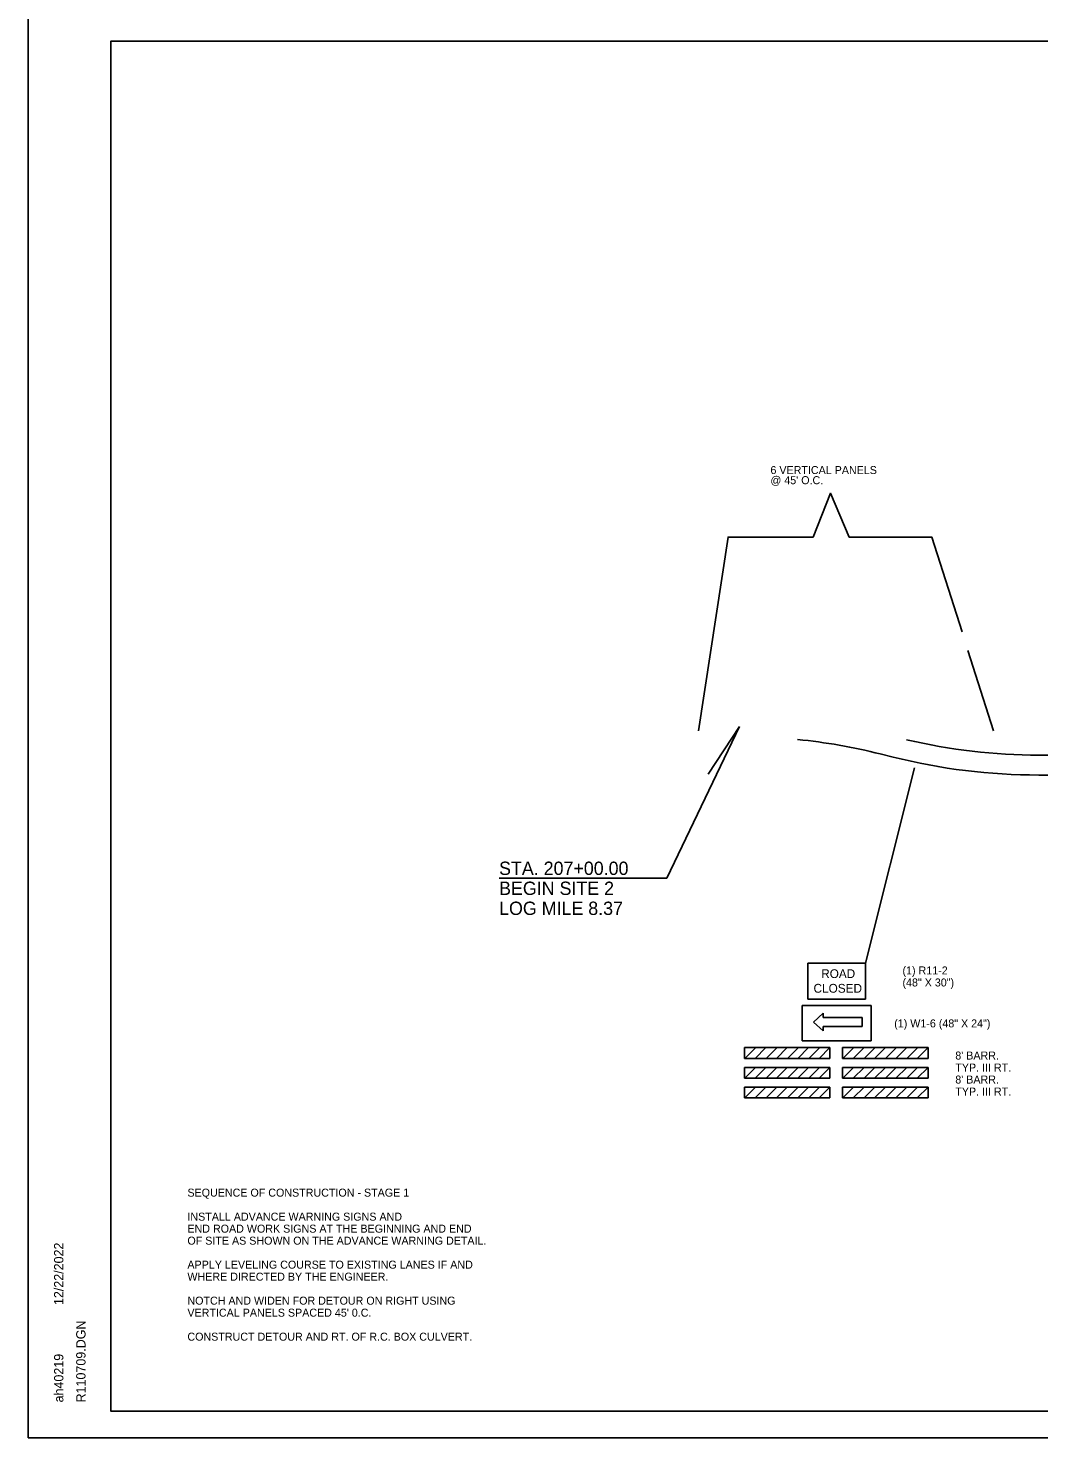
# Model space of a CAD drawing. Extents: x 2829243 to 2838161, y 467639 to 474695.
# Drawn here: x 2829486 to 2830244, y 470445 to 471502 of the extents above; entities that cross this region are included whole.
import ezdxf

# ---------------------------------------------------------------- set-up
doc = ezdxf.new("R2010")
doc.units = 0
for name, color, linetype in [('R_Border', 7, 'Continuous'), ('R_Border Notes', 7, 'Continuous'), ('R_Dimension', 7, 'Continuous'), ('R_MOT', 7, 'Continuous'), ('R_No Plot', 7, 'Continuous')]:
    doc.layers.add(name, color=color, linetype=linetype)

msp = doc.modelspace()

# ---------------------------------------------------------------- linework, layer by layer
at = {"layer": 'R_Border'}
for p, q in [((2829548.2, 471492.3), (2831129.1, 471492.3)), ((2829548.2, 470465), (2829548.2, 471492.3)), ((2829548.2, 470465), (2829548.2, 470465)), ((2831129.1, 470465), (2829548.2, 470465))]:
    msp.add_line(p, q, dxfattribs=at)
at = {"layer": 'R_Dimension'}
for p, q in [((2829965.2, 470864.6), (2830019.6, 470978.4)), ((2829996, 470942.8), (2830019.6, 470978.4)), ((2829965.2, 470864.6), (2829839.3, 470864.6))]:
    msp.add_line(p, q, dxfattribs=at)
at = {"layer": 'R_MOT'}
for p, q in [((2830070.7, 470773.9), (2830070.7, 470801)), ((2830070.7, 470801), (2830114.1, 470801)), ((2830114.1, 470773.9), (2830114.1, 470801)), ((2830070.7, 470773.9), (2830114.1, 470773.9)), ((2830075, 470756.8), (2830082.2, 470763.4)), ((2830082.2, 470750.3), (2830075, 470756.8)), ((2830082.2, 470760.1), (2830082.2, 470763.4)), ((2830111.6, 470760.1), (2830082.2, 470760.1)), ((2830111.6, 470753.5), (2830111.6, 470760.1)), ((2830111.6, 470753.5), (2830082.2, 470753.5)), ((2830082.2, 470753.5), (2830082.2, 470750.3)), ((2830023.4, 470737.7), (2830087.4, 470737.7)), ((2830023.4, 470729.6), (2830023.4, 470737.7)), ((2830087.4, 470729.6), (2830087.4, 470737.7)), ((2830096.9, 470737.7), (2830161, 470737.7)), ((2830096.9, 470729.6), (2830096.9, 470737.7)), ((2830161, 470729.6), (2830161, 470737.7)), ((2830023.4, 470729.6), (2830087.4, 470729.6)), ((2830087.4, 470729.6), (2830087.4, 470729.7)), ((2830096.9, 470729.6), (2830161, 470729.6)), ((2830160.9, 470729.6), (2830161, 470729.7)), ((2830023.4, 470722.8), (2830087.4, 470722.8)), ((2830023.4, 470714.7), (2830023.4, 470722.8)), ((2830023.4, 470714.7), (2830087.4, 470714.7)), ((2830087.4, 470714.7), (2830087.4, 470722.8)), ((2830087.4, 470714.7), (2830087.4, 470722.8)), ((2830096.9, 470722.8), (2830161, 470722.8)), ((2830096.9, 470714.7), (2830096.9, 470722.8)), ((2830096.9, 470714.7), (2830161, 470714.7)), ((2830161, 470714.7), (2830161, 470722.8)), ((2830161, 470714.7), (2830161, 470722.8)), ((2830023.4, 470707.9), (2830087.4, 470707.9)), ((2830023.4, 470699.9), (2830023.4, 470707.9)), ((2830087.4, 470699.9), (2830087.4, 470707.9)), ((2830096.9, 470707.9), (2830161, 470707.9)), ((2830096.9, 470699.9), (2830096.9, 470707.9)), ((2830161, 470699.9), (2830161, 470707.9)), ((2830023.4, 470699.9), (2830087.4, 470699.9)), ((2830096.9, 470699.9), (2830161, 470699.9))]:
    msp.add_line(p, q, dxfattribs=at)
for points in [[(2830186.5, 471049.3), (2830163.8, 471120.4), (2830101.8, 471120.4), (2830087.8, 471153.3), (2830074.8, 471120.4), (2830011, 471120.4), (2829988.9, 470975.2)], [(2830210.1, 470975.2), (2830190.9, 471035.4)], [(2830114.1, 470801), (2830150.9, 470947.4)]]:
    msp.add_lwpolyline(points, dxfattribs=at)
for points in [[(2830066.6, 470742.8), (2830118.2, 470742.8), (2830118.2, 470769.1), (2830066.6, 470769.1)], [(2830039.4, 470737.7), (2830031.6, 470737.6), (2830023.6, 470729.6), (2830031.4, 470729.6)], [(2830055.4, 470737.7), (2830047.6, 470737.6), (2830039.6, 470729.6), (2830047.4, 470729.6)], [(2830071.4, 470737.7), (2830063.6, 470737.6), (2830055.6, 470729.6), (2830063.4, 470729.6)], [(2830087.4, 470737.7), (2830079.6, 470737.6), (2830071.6, 470729.6), (2830079.4, 470729.6)], [(2830113, 470737.7), (2830105.1, 470737.6), (2830097.1, 470729.6), (2830104.9, 470729.6)], [(2830129, 470737.7), (2830121.1, 470737.6), (2830113.1, 470729.6), (2830120.9, 470729.6)], [(2830145, 470737.7), (2830137.1, 470737.6), (2830129.1, 470729.6), (2830136.9, 470729.6)], [(2830161, 470737.7), (2830153.1, 470737.6), (2830145.1, 470729.6), (2830152.9, 470729.6)], [(2830039.4, 470722.8), (2830031.6, 470722.7), (2830023.6, 470714.7), (2830031.4, 470714.7)], [(2830055.4, 470722.8), (2830047.6, 470722.7), (2830039.6, 470714.7), (2830047.4, 470714.7)], [(2830071.4, 470722.8), (2830063.6, 470722.7), (2830055.6, 470714.7), (2830063.4, 470714.7)], [(2830087.4, 470722.8), (2830079.6, 470722.7), (2830071.6, 470714.7), (2830079.4, 470714.7)], [(2830113, 470722.8), (2830105.1, 470722.7), (2830097.1, 470714.7), (2830104.9, 470714.7)], [(2830129, 470722.8), (2830121.1, 470722.7), (2830113.1, 470714.7), (2830120.9, 470714.7)], [(2830145, 470722.8), (2830137.1, 470722.7), (2830129.1, 470714.7), (2830136.9, 470714.7)], [(2830161, 470722.8), (2830153.1, 470722.7), (2830145.1, 470714.7), (2830152.9, 470714.7)], [(2830039.4, 470707.9), (2830031.6, 470707.9), (2830023.6, 470699.9), (2830031.4, 470699.9)], [(2830055.4, 470707.9), (2830047.6, 470707.9), (2830039.6, 470699.9), (2830047.4, 470699.9)], [(2830071.4, 470707.9), (2830063.6, 470707.9), (2830055.6, 470699.9), (2830063.4, 470699.9)], [(2830087.4, 470707.9), (2830079.6, 470707.9), (2830071.6, 470699.9), (2830079.4, 470699.9)], [(2830113, 470707.9), (2830105.1, 470707.9), (2830097.1, 470699.9), (2830104.9, 470699.9)], [(2830129, 470707.9), (2830121.1, 470707.9), (2830113.1, 470699.9), (2830120.9, 470699.9)], [(2830145, 470707.9), (2830137.1, 470707.9), (2830129.1, 470699.9), (2830136.9, 470699.9)], [(2830161, 470707.9), (2830153.1, 470707.9), (2830145.1, 470699.9), (2830152.9, 470699.9)]]:
    msp.add_lwpolyline(points, close=True, dxfattribs=at)
at = {"layer": 'R_No Plot'}
for p, q in [((2830125.1, 470957.9), (2830134.8, 470955.4)), ((2830244, 470956.9), (2830365.9, 470956.9)), ((2830244, 470941.9), (2830365.9, 470941.9)), ((2829486.2, 470445.1), (2831152.9, 470445.1))]:
    msp.add_line(p, q, dxfattribs=at)
for points in [[(2829486.2, 471511.8), (2831152.9, 471511.8), (2831152.9, 470445.1), (2829486.2, 470445.1)], [(2830717.8, 471492.3), (2830815.9, 471492.3), (2830815.9, 471442.9), (2830896.5, 471442.9), (2831012.5, 471442.9), (2831012.5, 471321.2), (2831129.1, 471321.2), (2831129.1, 470465), (2829548.2, 470465), (2829548.2, 471492.3)]]:
    msp.add_lwpolyline(points, close=True, dxfattribs=at)
for centre, radius, start, end in [((2830019.6, 470537.7), 433.2, 75.8983, 84.2308), ((2830244, 471390.2), 433.2, 256.7695, 270), ((2830244, 471390.2), 448.2, 255.8983, 270)]:
    msp.add_arc(centre, radius, start, end, dxfattribs=at)

# ---------------------------------------------------------------- texts
at = {"layer": 'R_Border'}
for s, p in [('12/22/2022', (2829512.6, 470544.6)), ('R110709.DGN', (2829529.2, 470471.6)), ('ah40219', (2829512.6, 470471.6))]:
    msp.add_text(s, height=7, rotation=90, dxfattribs=at).set_placement(p)
at = {"layer": 'R_Border Notes'}
for s, p in [('SEQUENCE OF CONSTRUCTION - STAGE 1', (2829605.6, 470625.9)), ('INSTALL ADVANCE WARNING SIGNS AND ', (2829605.6, 470607.9)), ('END ROAD WORK SIGNS AT THE BEGINNING AND END', (2829605.6, 470598.9)), ('OF SITE AS SHOWN ON THE ADVANCE WARNING DETAIL.', (2829605.6, 470589.9)), ('APPLY LEVELING COURSE TO EXISTING LANES IF AND', (2829605.6, 470571.9)), ('WHERE DIRECTED BY THE ENGINEER.', (2829605.6, 470562.9)), ('NOTCH AND WIDEN FOR DETOUR ON RIGHT USING', (2829605.6, 470544.9)), ("VERTICAL PANELS SPACED 45' 0.C.", (2829605.6, 470535.9)), ('CONSTRUCT DETOUR AND RT. OF R.C. BOX CULVERT.', (2829605.6, 470517.9))]:
    msp.add_text(s, height=6, dxfattribs=at).set_placement(p)
at = {"layer": 'R_Dimension'}
for s, p in [('STA. 207+00.00', (2829839.3, 470867.1)), ('BEGIN SITE 2', (2829839.3, 470852.1)), ('LOG MILE 8.37', (2829839.3, 470837.1))]:
    msp.add_text(s, height=10, rotation=0.0006, dxfattribs=at).set_placement(p)
at = {"layer": 'R_MOT'}
for s, p in [('6 VERTICAL PANELS', (2830042.8, 471167.7)), ("@ 45' O.C.", (2830042.8, 471160.1))]:
    msp.add_text(s, height=6, rotation=0.0055, dxfattribs=at).set_placement(p)
for s, height, p in [('(1) R11-2', 6, (2830141.8, 470792.5)), ('ROAD', 6.58, (2830080.9, 470789.8)), ('(48" X 30")', 6, (2830141.8, 470783.5)), ('CLOSED', 6.61, (2830075.1, 470778.8)), ('(1) W1-6 (48" X 24")', 6, (2830135.6, 470752.8)), ("8' BARR.", 6, (2830181.4, 470728.7)), ('TYP. III RT.', 6, (2830181.4, 470719.7)), ("8' BARR.", 6, (2830181.4, 470710.7)), ('TYP. III RT.', 6, (2830181.4, 470701.7))]:
    msp.add_text(s, height=height, dxfattribs=at).set_placement(p)

doc.saveas('drawing.dxf')
